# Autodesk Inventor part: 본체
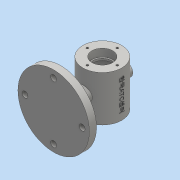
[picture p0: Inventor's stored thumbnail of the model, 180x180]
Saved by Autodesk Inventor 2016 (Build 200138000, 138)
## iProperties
Created: 2018-12
Part Number: 본체
Material: 일반
Document SubType Name: Modeling
Designer: 3sil_cad0123
Density: 1 g/cm^3
Appearance: 기본값
Author: 3sil_cad0123
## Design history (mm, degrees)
sketch "스케치2"
  geometry: C1 r 30 at (0, 0); C2 r 14 at (0, 0); C3 r 25 at (0, 0); 1 further point
  constraints: 3 centre point, 3 coincident
  dimensions: "d3" = 60 diameter of C1; "d4" = 28 diameter of C2; "d5" = 50 diameter of C3
extrude "돌출1" new body sketch "스케치2" stored distance "d6" = 70; taper "d7" = 0 deg
extrude "돌출2" cut sketch "스케치2" stored distance "d8" = 70; taper "d9" = 0 deg
extrude "돌출3" cut sketch "스케치2" stored distance "d10" = 40; taper "d11" = 0 deg
sketch "스케치3" dims "d13" = 46
  geometry: L1 (0, 0)-(0, 23); C1 r 14 at (0, 0) reference; C2 r 30 at (0, 0) reference; C3 r 16 at (0, 0); C4 r 1.692 at (0, 23)
  constraints: 3 coincident, 2 centre point, 2 end point, 1 vertical, 1 vertical alignment, 2 other
  dimensions: "d12" = 32 diameter of C3
extrude "돌출4" cut sketch "스케치3" distance "d14" = 12; taper "d15" = 0 deg
sketch "스케치4" dims "d16" = 46
  geometry: L1 (0, 23)-(0, 26.218); C1 r 30 at (0, 0) reference; 1 further point
  constraints: 2 end point, 1 coincident, 1 vertical, 1 vertical alignment, 2 other
hole "구멍1" sketch "스케치4" at (0, 23) diameter "d17" = 3.242; stored, may be unused: countersink angle "d21" = 90 deg, drill point angle "d23" = 118 deg; dims "d18" = 8, "d19" = 4, "d20" = 2, "d22" = 10
node "작업 평면1"
sketch "스케치5"
  geometry: L1 (0, -75)-(55, -75); L2 (55, -75)-(55, -64); L3 (0, -58.127)-(0, -75); L4 (0, -75)-(12, -75); L5 (12, -52.478)-(12, -26.195); L6 (12, -26.195)-(0, -26.195); L7 (0, -26.195)-(0, -75); L8 (55, -64)-(12, -52.478); L9 (0, 27.709)-(10, 27.709); L10 (10, 27.709)-(10, 37); L11 (10, 37)-(0, 37); L12 (0, 37)-(0, 27.709); 1 further point
  constraints: 24 end point, 5 parallel, 3 horizontal, 3 perpendicular
  dimensions: "d27" = 55 distance of L1.start L1.end; "d29" = 75 deg angle of L2 L8; "d30" = 12 distance between parallel lines of L5 L7; "d31" = 75 distance from line of point (0, 0) L1; "d32" = 11 distance of L1.end L2.end; "d33" = 10 distance of L10.end L11.end; "d34" = 112 distance between parallel lines of L11 L1
revolve "회전1" stored, may be unused: angle "d35" = 90 deg
revolve "회전2" stored, may be unused: angle "d36" = 90 deg
sketch "스케치6"
  geometry: C1 r 10 at (0, 0) reference; C2 r 5 at (0, 0)
  constraints: 1 centre point, 1 coincident
  dimensions: "d37" = 10 diameter of C2
extrude "돌출5" cut sketch "스케치6" distance "d38" = 27.5; taper "d39" = 0 deg
sketch "스케치7" dims "d41" = 88
  geometry: C1 r 5 at (0, 0) reference; C2 r 4.5 at (0, 44); 1 further point
  constraints: 1 centre point, 1 coincident, 1 vertical alignment, 2 other
  dimensions: "d40" = 9 diameter of C2
extrude "돌출6" cut sketch "스케치7" distance "d42" = 27.5; taper "d43" = 0 deg
node "작업 평면2"
sketch "스케치8"
  geometry: C1 r 7 at (0, 44); 3 further points
  constraints: 1 centre point, 1 coincident, 2 other
  dimensions: "d45" = 14 diameter of C1
extrude "돌출7" cut sketch "스케치8" distance "d46" = 27.5; taper "d47" = 0 deg
node "작업 평면3"
sketch "스케치9"
  geometry: L1 (3.495, 24.345)-(3.495, 10.268); L2 (3.495, 10.268)-(-40.465, 10.268); L3 (-40.465, 10.268)-(-40.465, 24.345); L4 (-40.465, 24.345)-(3.495, 24.345); 1 further point
  constraints: 2 other
extrude "돌출8" join sketch "스케치9" stored distance "d52" = 27.5; taper "d53" = 0 deg
node "솔리드1"
pattern_circular "원형 패턴1" dims angle "d25" = 360 deg
mirror "대칭1"
pattern_circular "원형 패턴2" dims angle "d49" = 360 deg
other parameters: "d51" = 30.5
